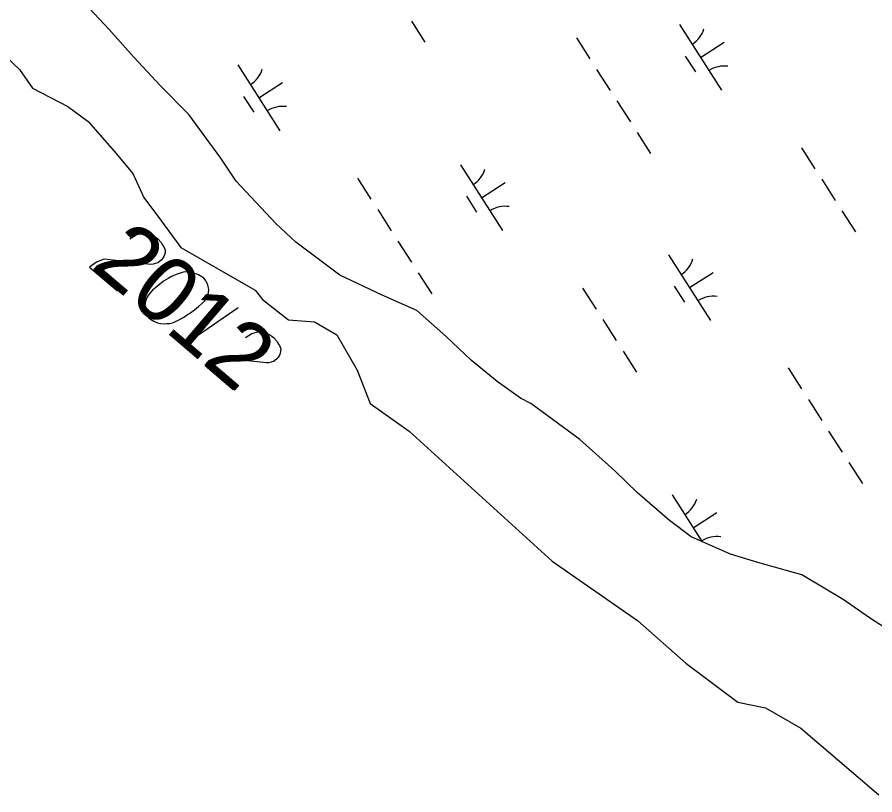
# Model space of a CAD drawing. Extents: x 3962991 to 3983549, y 181631 to 204078.
# Drawn here: x 3975877 to 3976425, y 192285 to 192782 of the extents above; entities that cross this region are included whole.
import ezdxf

# ---------------------------------------------------------------- set-up
doc = ezdxf.new("R2010")
doc.units = 0
for name, color, linetype in [('V-ANNO-MASK', 7, 'Continuous'), ('V-ANNO-MASK2', 7, 'Continuous'), ('V-RIVR-EDGE', 7, 'Continuous'), ('V-RIVR-IDEN', 7, 'Continuous'), ('V-WETL-SWMP', 7, 'Continuous')]:
    doc.layers.add(name, color=color, linetype=linetype)

msp = doc.modelspace()

# ---------------------------------------------------------------- linework, layer by layer
at = {"layer": 'V-ANNO-MASK2'}
msp.add_line((3976018.31, 192596.47), (3975982.49, 192571.82), dxfattribs=at)
for points in [[(3975948.91, 192640.47), (3975952.93, 192643.13), (3975957.51, 192644.44), (3975960.85, 192643.76), (3975963.76, 192642.58), (3975965.73, 192641.33), (3975966.99, 192640.26), (3975969.04, 192638.08), (3975970.12, 192636.29), (3975970.66, 192635.39), (3975971.53, 192633.35), (3975971.42, 192631.7), (3975971.07, 192630.26), (3975970.68, 192629.29), (3975970.07, 192628.07), (3975968.99, 192626.81), (3975967.67, 192625.77), (3975966.77, 192625.23), (3975965.41, 192624.65), (3975963.8, 192624.29), (3975962.4, 192624.18), (3975932.58, 192627.45), (3975927.57, 192625.65), (3975923.13, 192622.48), (3975940.99, 192607.24)], [(3975996.17, 192615.36), (3975995.67, 192615.79), (3975993.95, 192616.82), (3975992.73, 192617.43), (3975991.76, 192617.82), (3975990.07, 192618.39), (3975987.92, 192618.93), (3975986.01, 192619.25), (3975983.9, 192619.31), (3975982.28, 192618.95), (3975980.46, 192618.34), (3975978.63, 192617.72), (3975976.59, 192616.86), (3975975.22, 192616.28), (3975973.43, 192615.2), (3975970.53, 192613.33), (3975966.56, 192610.2), (3975963.48, 192607.61), (3975961.12, 192604.84), (3975959.65, 192602.62), (3975958.72, 192599.49), (3975958.4, 192597.59), (3975958.37, 192595.01), (3975959.03, 192592.71), (3975959.57, 192591.82), (3975960.86, 192590.28), (3975962.12, 192589.21), (3975964.34, 192587.74), (3975966.54, 192586.74), (3975968.44, 192586.42), (3975971.27, 192586.18), (3975972.67, 192586.29), (3975974.53, 192586.43), (3975976.15, 192586.8), (3975977.3, 192587.12), (3975978.87, 192587.95), (3975979.55, 192588.24), (3975981.13, 192589.07), (3975982.92, 192590.15), (3975984.71, 192591.23), (3975985.82, 192592.02), (3975986.72, 192592.56), (3975987.83, 192593.35), (3975990.26, 192595.19), (3975991.59, 192596.23), (3975992.91, 192597.27), (3975994.67, 192598.82), (3975996.85, 192600.87), (3975997.49, 192601.62), (3975998.1, 192602.84), (3975998.71, 192604.06), (3975999.24, 192606.22), (3975999.35, 192607.87), (3975999.24, 192609.27), (3975998.87, 192610.88), (3975998.3, 192612.24), (3975997.76, 192613.14), (3975997.22, 192614.03), (3975996.17, 192615.36)], [(3976022.87, 192577.36), (3976026.88, 192580.02), (3976031.47, 192581.32), (3976034.81, 192580.65), (3976037.72, 192579.47), (3976039.69, 192578.22), (3976040.95, 192577.15), (3976043, 192574.96), (3976044.08, 192573.17), (3976044.62, 192572.27), (3976045.49, 192570.23), (3976045.38, 192568.58), (3976045.03, 192567.15), (3976044.63, 192566.18), (3976044.03, 192564.96), (3976042.95, 192563.7), (3976041.63, 192562.66), (3976040.73, 192562.12), (3976039.37, 192561.54), (3976037.76, 192561.18), (3976036.36, 192561.07), (3976006.54, 192564.34), (3976001.53, 192562.53), (3975997.08, 192559.37), (3976014.95, 192544.12)]]:
    msp.add_lwpolyline(points, dxfattribs=at)
at = {"layer": 'V-RIVR-EDGE'}
msp.add_lwpolyline([(3975860.53, 192765.52), (3975878.34, 192748.89), (3975886.65, 192737.02), (3975909.21, 192725.15), (3975922.27, 192715.65), (3975938.89, 192696.66), (3975950.76, 192682.41), (3975957.88, 192666.98), (3975968.57, 192652.73), (3975981.63, 192634.92), (3976029.12, 192607.62), (3976033.86, 192601.68), (3976050.49, 192588.62), (3976067.11, 192587.43), (3976081.35, 192579.12), (3976094.41, 192556.57), (3976102.72, 192535.2), (3976127.65, 192517.39), (3976219.07, 192434.28), (3976273.68, 192396.29), (3976304.55, 192368.99), (3976337.79, 192344.06), (3976355.6, 192340.49), (3976378.16, 192327.43), (3976428.02, 192284.69)], dxfattribs=at)
at = {"layer": 'V-WETL-SWMP'}
for p, q in [((3976128.99, 192779.91), (3976137.63, 192766.44)), ((3976300.44, 192777.66), (3976327.42, 192735.57)), ((3976234.56, 192769.19), (3976243.19, 192755.72)), ((3976313.93, 192756.61), (3976329.08, 192766.33)), ((3976304.2, 192757.5), (3976310.67, 192747.4)), ((3976017.96, 192751.84), (3976044.94, 192709.74)), ((3976247.51, 192748.98), (3976256.15, 192735.51)), ((3976031.45, 192730.79), (3976046.6, 192740.51)), ((3976021.72, 192731.68), (3976028.19, 192721.58)), ((3976260.46, 192728.78), (3976269.1, 192715.31)), ((3976273.42, 192708.57), (3976282.05, 192695.1)), ((3976378.56, 192698.82), (3976387.19, 192685.35)), ((3976160.41, 192687.89), (3976187.39, 192645.79)), ((3976094.53, 192679.41), (3976103.16, 192665.94)), ((3976173.9, 192666.84), (3976189.05, 192676.56)), ((3976391.51, 192678.62), (3976400.15, 192665.15)), ((3976164.17, 192667.73), (3976170.64, 192657.63)), ((3976107.48, 192659.21), (3976116.11, 192645.74)), ((3976404.46, 192658.41), (3976413.1, 192644.94)), ((3976120.43, 192639), (3976129.07, 192625.53)), ((3976293.43, 192630.34), (3976320.42, 192588.25)), ((3976133.38, 192618.8), (3976142.02, 192605.33)), ((3976306.92, 192609.3), (3976322.08, 192619.01)), ((3976297.19, 192610.19), (3976303.67, 192600.08)), ((3976238.53, 192609.05), (3976247.16, 192595.58)), ((3976251.48, 192588.84), (3976260.11, 192575.37)), ((3976264.43, 192568.64), (3976273.07, 192555.17)), ((3976370, 192557.92), (3976378.63, 192544.45)), ((3976382.95, 192537.71), (3976391.59, 192524.25)), ((3976395.91, 192517.51), (3976404.54, 192504.04)), ((3976408.86, 192497.31), (3976417.49, 192483.84)), ((3976295.85, 192476.62), (3976315.08, 192446.62)), ((3976309.34, 192455.57), (3976324.49, 192465.29)), ((3976299.61, 192456.46), (3976300.01, 192455.84))]:
    msp.add_line(p, q, dxfattribs=at)
msp.add_lwpolyline([(3976435.93, 192389.1), (3976422.09, 192397.89), (3976405.23, 192409.64), (3976378.77, 192425.46), (3976350.61, 192433.49), (3976333.23, 192438.66), (3976308.02, 192449.71), (3976294.17, 192460.3), (3976273.66, 192477.98), (3976259.16, 192492.14), (3976236.83, 192512.18), (3976205.51, 192535.11), (3976198.9, 192538.62), (3976183.85, 192549.19), (3976167.56, 192562.74), (3976151.26, 192578.07), (3976132.56, 192594.58), (3976110.35, 192604.47), (3976083.32, 192617.29), (3976055.01, 192638.46), (3976042.33, 192650.26), (3976016.93, 192677.43), (3976007.21, 192692.25), (3975986.58, 192720.07), (3975968.45, 192738.38), (3975951.51, 192756.69), (3975935.78, 192774.42), (3975923.08, 192788.01)], dxfattribs=at)
for centre, start, end in [((3976299.22, 192780), 301.8919, 343.4355), ((3976016.74, 192754.17), 301.8919, 343.4355), ((3976329.04, 192733.49), 81.8919, 123.4355), ((3976046.56, 192707.67), 81.8919, 123.4355), ((3976159.19, 192690.22), 301.8919, 343.4355), ((3976189.01, 192643.72), 81.8919, 123.4355), ((3976292.22, 192632.68), 301.8919, 343.4355), ((3976322.03, 192586.17), 81.8919, 123.4355), ((3976294.63, 192478.96), 301.8919, 343.4355), ((3976324.45, 192432.45), 81.8919, 123.4355)]:
    msp.add_arc(centre, 17.62, start, end, dxfattribs=at)

# ---------------------------------------------------------------- texts
at = {"layer": 'V-ANNO-MASK'}
msp.add_text('2012', height=42, rotation=319.5233, dxfattribs=at).set_placement((3975923.13, 192622.48))
at = {"layer": 'V-RIVR-IDEN'}
msp.add_text('2012', height=42, rotation=319.5233, dxfattribs=at).set_placement((3975923.13, 192622.48))

doc.saveas('drawing.dxf')
